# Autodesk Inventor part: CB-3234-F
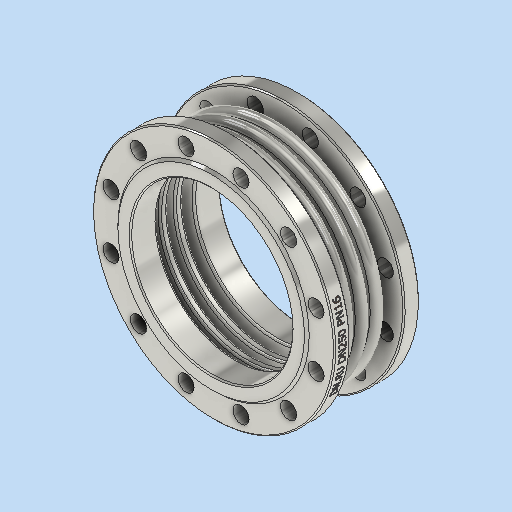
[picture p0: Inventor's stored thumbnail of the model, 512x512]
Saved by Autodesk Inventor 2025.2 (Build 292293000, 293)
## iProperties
Company: DN.RU
Created: 2026-04
Part Number: CB-3234-F
Material: Типовые
Document SubType Name: Modeling
Designer: DN.RU
Density: 5.61325 g/cm^3
Appearance: По умолчанию
Description: D140-02120
Mass: 25500 g
Surface Area: 10932.5 cm^2
Volume: 4542.82 cm^3
Author: DN.RU
Title: Компенсатор сильфонный осевой DN.ru Ду250 Ру16
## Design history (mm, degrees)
sketch "Эскиз1"
  geometry: L1 (0, 0)-(0, -75); L2 (145, -75)-(145, 0); L3 (145, 0)-(0, 0); L4 (145, 0)-(145, 0); L5 (115, 0)-(175, 0); L6 (115, -9)-(175, -9); L7 (175, 9)-(115, 9); L8 (175, -6)-(115, -6); L9 (115, 6)-(175, 6); L10 (175, -16)-(115, -16); L11 (115, -19)-(175, -19); L12 (115, -25)-(175, -25); L13 (115, -34)-(175, -34); L14 (175, -31)-(115, -31); L15 (0, -75)-(145, -75); L16 (145, -75)-(135, -75); L17 (135, -75)-(135, -31); L18 (145, -19)-(142, -19); L19 (142, -19)-(142, -6); L20 (145, 6)-(142, 6); L21 (142, 6)-(142, 0); L22 (0, -75)-(0, -45); L23 (0, -45)-(202.5, -45); L24 (202.5, -45)-(202.5, -75); L25 (202.5, -75)-(0, -75); L26 (145, -45)-(145, -63); L27 (145, -63)-(150, -63); L28 (150, -63)-(150, -45); L29 (150, -45)-(145, -45); L30 (145, 0)-(184, 0); A1 r 9 centre (115, 0) between (115, 9) and (115, -9); A2 r 9 centre (175, 0) between (175, -9) and (175, 9); A3 r 6 centre (115, 0) between (115, 6) and (115, -6); A4 r 6 centre (175, 0) between (175, -6) and (175, 6); A5 r 6 centre (115, -25) between (115, -19) and (115, -31); A6 r 9 centre (115, -25) between (115, -16) and (115, -34); A7 r 6 centre (175, -25) between (175, -31) and (175, -19); A8 r 9 centre (175, -25) between (175, -34) and (175, -16); 20 further points
  constraints: 64 end point, 17 point on circle, 14 point on line, 8 centre point, 7 parallel, 5 perpendicular, 4 tangent, 3 midpoint, 2 vertical, 1 horizontal, 25 other
  dimensions: "d0" = 75 distance of L1.start L1.end; "d3" = 0 distance of L2.end L4.end; "d4" = 30 distance of L4.end L5.end; "d5" = 18 diameter of A2; "d6" = 3 distance between parallel lines of L6 L8; "d9" = 25 distance of L4.end point (145, -25); "d18" = 3 distance of L18.start L18.end; "d19" = 3 distance of L20.start L20.end; "d27" = 135 distance between parallel lines of L1 L17; "d28" = 10 distance between parallel lines of L2 L17; "d29" = 30 distance of L1.end L22.end; "d30" = 202.5 distance of L22.end L23.end; "d31" = 18 distance of L26.start L26.end; "d32" = 5 distance of L27.end L26.end
revolve "Вращение1" sketch "Эскиз1" stored, may be unused: angle "d20" = 360 deg
sketch "Эскиз3" dims "d33" = 355
  geometry: L1 (0, 0)-(74.331, 19.917); L2 (0, 0)-(76.954, 0); C1 r 13.5 at (171.452, 45.94); C2 r 13.5 at (125.511, 125.511); C3 r 13.5 at (45.94, 171.452); C4 r 13.5 at (-45.94, 171.452); C5 r 135 at (0, 0) reference; C6 r 160 at (0, 0); C7 r 202.5 at (0, 0) reference; C8 r 13.5 at (-125.511, 125.511); C9 r 13.5 at (-171.452, 45.94); C10 r 13.5 at (-171.452, -45.94); C11 r 13.5 at (-125.511, -125.511); C12 r 13.5 at (-45.94, -171.452); C13 r 13.5 at (45.94, -171.452); C14 r 13.5 at (125.511, -125.511); C15 r 13.5 at (171.452, -45.94); 1 further point
  constraints: 13 centre point, 4 end point, 2 coincident, 1 equal length, 1 horizontal, 1 point on line, 28 other
  dimensions: "d34" = 15 deg angle of L2 L1; "d35" = 27 diameter of C1; "d38" = 360 deg dimension on point (0, 0) C1.centre (derived); "d40" = 320 diameter of C6
  node "Эскиз — круговой массив1" dims "d38" = 360 deg (derived)
extrude "Выдавливание1" cut sketch "Эскиз3" stored distance "d41" = 10; taper "d42" = 0 deg
extrude "Выдавливание2" cut sketch "Эскиз3" distance "d43" = 4; taper "d44" = 0 deg
chamfer "Фаска2" distance "d45" = 4; stored, may be unused: second distance "d46" = 2, angle "d47" = 45 deg
chamfer "Фаска3" distance "d48" = 2; stored, may be unused: second distance "d49" = 2, angle "d50" = 45 deg
mirror "Зеркальное отражение2"
fillet "Сопряжение2" dims "d51" = 3
node "РабПлоскость2"
sketch "Эскиз4"
  geometry: L1 (-79.676, 4.102)-(96.959, 4.102); L2 (96.959, 4.102)-(96.959, -37.018); L3 (96.959, -37.018)-(-79.676, -37.018); L4 (-79.676, -37.018)-(-79.676, 4.102); 1 further point
  constraints: 2 other
feature "Рельеф2" sketch "Эскиз4" dims "d52" = 0.1, "d53" = 0
feature "ɓ耀ɕ耀ɗ耀ə耀ɛ耀ɝ耀ɟ耀ɡ耀" dims "d0" = 75, "d3" = 0, "d4" = 30, "d5" = 18, "d6" = 3, "d7" = 20, "d9" = 25, "d10" = 10, "d12" = 10, "d18" = 3, "d19" = 3, "d20" = 360 deg, "d27" = 135, "d28" = 10, "d29" = 30, "d30" = 202.5, "d31" = 18, "d32" = 5, "d33" = 355, "d34" = 15 deg, "d35" = 27, "d36" = 120, "d38" = 360 deg (derived), "d40" = 320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
node "Твердое тело1"
node "Эскиз — прямоугольный массив1" dims "d9" = 25, "d12" = 10
